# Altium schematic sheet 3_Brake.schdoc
size 431 x 309 mm
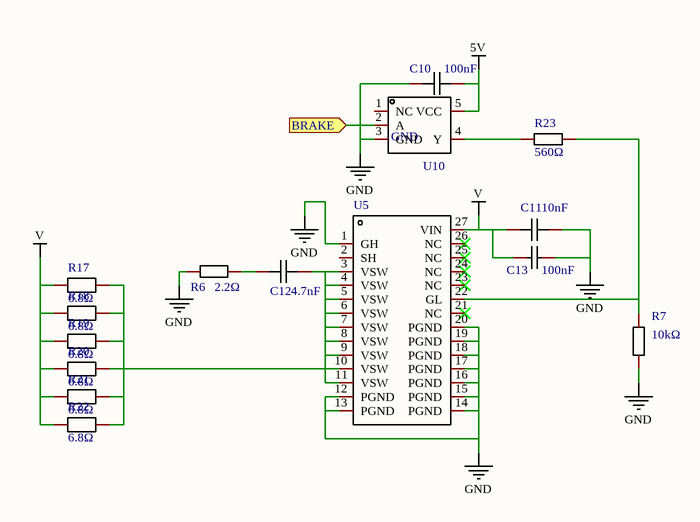
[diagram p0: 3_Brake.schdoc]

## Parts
C10  value 100nF  [C0402]  (hidden comment: CC0402KRX7R7BB104)
C11  value 10nF  [C0402]  (hidden comment: CC0402KRX7R0BB103)
C12  value 4.7nF  [C0402]  (hidden comment: GRM155R72A472KA01D)
C13  value 100nF  [C0805]  (hidden comment: CL21B104KCFNNNE)
R6  value 2.2Ω  [R0805]  (hidden comment: 0805W8F220KT5E)
R7  value 10kΩ  [R0402]  (hidden comment: 0402WGF1002TCE)
R17  value 6.8Ω  [R2512]  (hidden comment: RC2512JK-7W6R8L)
R18  value 6.8Ω  [R2512]  (hidden comment: RC2512JK-7W6R8L)
R19  value 6.8Ω  [R2512]  (hidden comment: RC2512JK-7W6R8L)
R20  value 6.8Ω  [R2512]  (hidden comment: RC2512JK-7W6R8L)
R21  value 6.8Ω  [R2512]  (hidden comment: RC2512JK-7W6R8L)
R22  value 6.8Ω  [R2512]  (hidden comment: RC2512JK-7W6R8L)
R23  value 560Ω  [R0402]  (hidden comment: 0402WGJ0561TCE)
U5  CSD88599Q5DCT  (value not drawn)
U10  NAME: GND  [SC-70-5_L2.1-W1.3-P0.65-LS2.1-BR]  (hidden comment: SN74LVC1G17DCKR)

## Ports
BRAKE (in)

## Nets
5V: C10.1 U10.5(VCC)
GND: C10.2 C11.2 C13.2 R6.1 R7.1 U5.1(GH) U5.12(PGND) U5.13(PGND) U5.14(PGND) U5.15(PGND) U5.16(PGND) U5.17(PGND) U5.18(PGND) U5.19(PGND) U5.20(PGND) U10.3(GND)
V: C11.1 C13.1 R17.2 R18.1 R19.1 R20.1 R21.1 R22.1 U5.27(VIN)
BRAKE: U10.2(A) ; port BRAKE
NetC12_1: C12.1 R6.2
NetC12_2: C12.2 R17.1 R18.2 R19.2 R20.2 R21.2 R22.2 U5.3(VSW) U5.4(VSW) U5.5(VSW) U5.6(VSW) U5.7(VSW) U5.8(VSW) U5.9(VSW) U5.10(VSW) U5.11(VSW)
NetR7_2: R7.2 R23.2 U5.22(GL)
NetR23_1: R23.1 U10.4(Y)

Not connected (* = marked no-connect by the designer): U5 2(SH) 21(NC)* 23(NC)* 24(NC)* 25(NC)* 26(NC)*; U10 1(NC)

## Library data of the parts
C10 = CC0402KRX7R7BB104: Capacitance:100nF Tolerance:±10% Tolerance:±10% Voltage Rated:16V Temperature Coefficient:X7R; Manufacturer: YAGEO(国巨); Add into BOM: yes; Tolerance: ±10%; Voltage Rated: 16V; Temperature Coefficient: X7R
C11 = CC0402KRX7R0BB103: Capacitance:10nF Tolerance:±10% Tolerance:±10% Voltage Rated:100V Temperature Coefficient:X7R; Manufacturer: YAGEO(国巨); Add into BOM: yes; Tolerance: ±10%; Voltage Rated: 100V; Temperature Coefficient: X7R
C12 = GRM155R72A472KA01D: Capacitance:4.7nF Tolerance:±10% Tolerance:±10% Voltage Rated:100V Temperature Coefficient:X7R; Manufacturer: muRata(村田); Add into BOM: yes; Tolerance: ±10%; Voltage Rated: 100V; Temperature Coefficient: X7R
C13 = CL21B104KCFNNNE: Capacitance:100nF Tolerance:±10% Tolerance:±10% Voltage Rated:100V Temperature Coefficient:X7R; Manufacturer: SAMSUNG(三星); Add into BOM: yes; Tolerance: ±10%; Voltage Rated: 100V; Temperature Coefficient: X7R
R6 = 0805W8F220KT5E: Type:厚膜电阻 Resistance:2.2Ω Tolerance:±1% Power(Watts):125mW Temperature Coefficient:±400ppm/ Temperature Coefficient:±400ppm/ Overload Voltage (Max):150V Operating Temperature Range:-55~+155 Operating Temperature Range:-55~+155; Manufacturer: UNI-ROYAL(厚声); Add into BOM: yes; Tolerance: ±1%; Power(Watts): 125mW; Overload Voltage (Max): 150V
R7 = 0402WGF1002TCE: Type:厚膜电阻 Resistance:10kΩ Tolerance:±1% Tolerance:±1% Power(Watts):1/16W Temperature Coefficient:±100ppm/ Temperature Coefficient:±100ppm/ Overload Voltage (Max):50V Operating Temperature Range:-55~+155 Operating Temperature Range:-55~+155; Manufacturer: UNI-ROYAL(厚声); Add into BOM: yes; Tolerance: ±1%; Power(Watts): 1/16W; Overload Voltage (Max): 50V
R17-R22 = RC2512JK-7W6R8L: Resistance:6.8Ω Tolerance:±5% Power(Watts):2W Temperature Coefficient:±200ppm/ Temperature Coefficient:±200ppm/; Manufacturer: YAGEO(国巨); Add into BOM: yes; Tolerance: ±5%; Power(Watts): 2W
R23 = 0402WGJ0561TCE: Type:厚膜电阻 Resistance:560Ω Tolerance:±5% Power(Watts):1/16W Temperature Coefficient:±100ppm/ Temperature Coefficient:±100ppm/ Overload Voltage (Max):50V Operating Temperature Range:-55~+155 Operating Temperature Range:-55~+155; Manufacturer: UNI-ROYAL(厚声); Add into BOM: yes; Tolerance: ±5%; Power(Watts): 1/16W; Overload Voltage (Max): 50V
U5 = CSD88599Q5DCT: Manufacturer: TI(德州仪器); Add into BOM: yes
U10 = SN74LVC1G17DCKR: Series:74LVC Logic Type:缓冲器，非反向 Number of Elements:1 Number of Bits per Element:1 Input Type:施密特触发器 Output Type:施密特触发器 Current - Output High, Low:32mA、32mA Voltage - Supply:1.65V ~ 5.5V Operating Temperature:-40~+125（TA）; Manufacturer: TI(德州仪器); Add into BOM: yes; Number of Elements: 1; Input Type: 施密特触发器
